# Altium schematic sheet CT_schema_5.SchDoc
size 145 x 108 mm
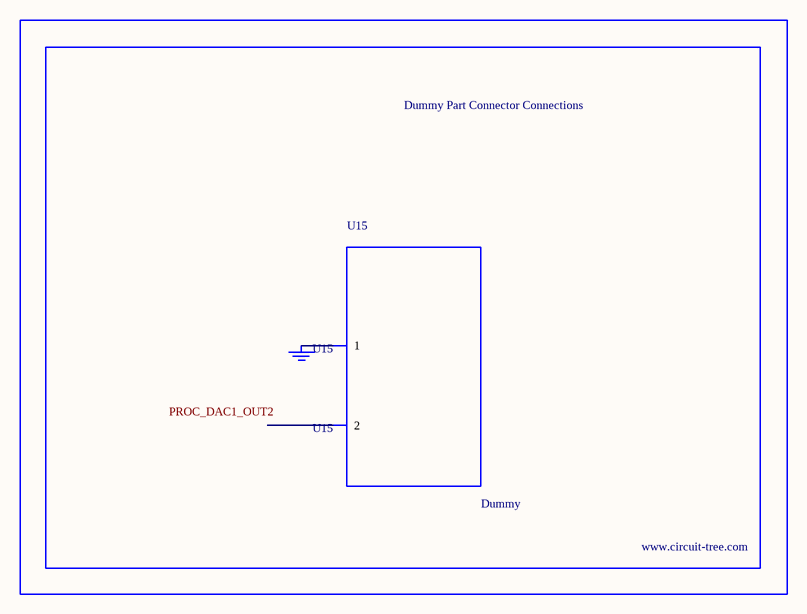
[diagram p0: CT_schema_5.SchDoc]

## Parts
BORDER4  (no value)
GND_INSTANCE_4_0  (no value)
U15  Dummy  [DUMMY_PACKAGE_127]

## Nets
NetGND_INSTANCE_4_0_0: GND_INSTANCE_4_0.0(GND) U15.1

Not connected (* = marked no-connect by the designer): U15 2

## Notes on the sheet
- Labels drawn without touching a wire or pin: PROC_DAC1_OUT2

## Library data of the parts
BORDER4 = BORDER_PAGE4
GND_INSTANCE_4_0 = GND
